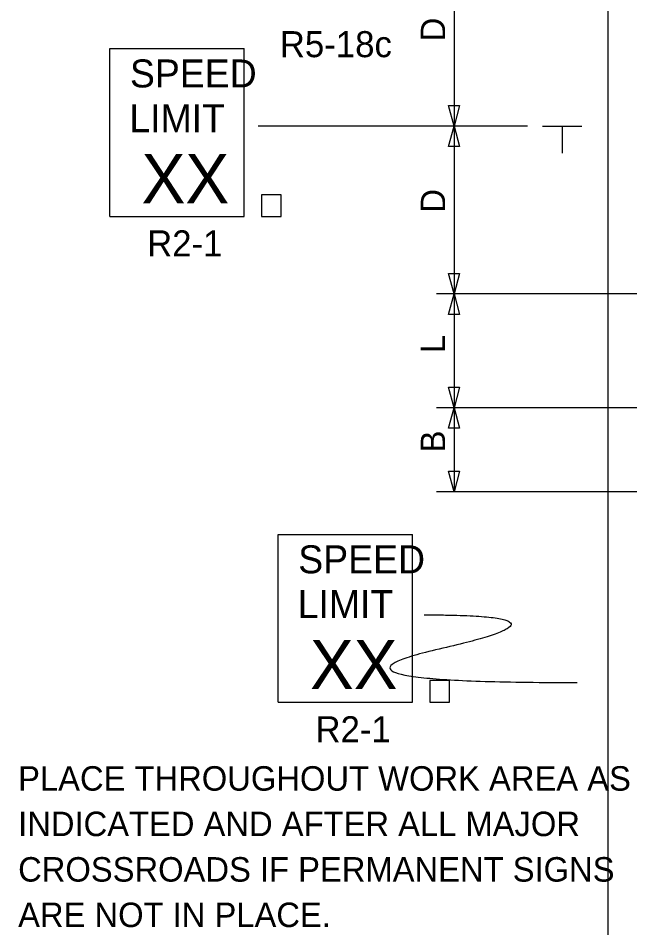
# Model space of a CAD drawing. Extents: x 16796 to 18475, y 7218 to 8209.
# Drawn here: x 16800.6 to 16975.6, y 7711.6 to 7971.7 of the extents above; entities that cross this region are included whole.
import ezdxf

# ---------------------------------------------------------------- set-up
doc = ezdxf.new("R2010")
doc.units = 0
for name, color, linetype in [('PAVT_EDGE_EX', 7, 'Continuous'), ('TRAFFIC_SIGNS_PR', 7, 'Continuous'), ('TYPICAL_TEXT_DIMEN_PR', 7, 'Continuous')]:
    doc.layers.add(name, color=color, linetype=linetype)

msp = doc.modelspace()

# ---------------------------------------------------------------- linework, layer by layer
at = {"layer": 'PAVT_EDGE_EX'}
msp.add_line((16969.33, 8204.89), (16969.33, 7353.77), dxfattribs=at)
at = {"layer": 'TRAFFIC_SIGNS_PR'}
for p, q in [((16826.84, 7963), (16865.24, 7963)), ((16826.84, 7915), (16826.84, 7963)), ((16865.24, 7915), (16865.24, 7963)), ((16826.84, 7915), (16865.24, 7915)), ((16875, 7824.09), (16913.4, 7824.09)), ((16875, 7776.09), (16875, 7824.09)), ((16913.4, 7776.09), (16913.4, 7824.09)), ((16875, 7776.09), (16913.4, 7776.09))]:
    msp.add_line(p, q, dxfattribs=at)
for points in [[(16870.26, 7915), (16875.85, 7915), (16875.85, 7921.17), (16870.26, 7921.17)], [(16918.41, 7776.09), (16924.01, 7776.09), (16924.01, 7782.26), (16918.41, 7782.26)]]:
    msp.add_lwpolyline(points, close=True, dxfattribs=at)
msp.add_open_spline([(16916.81, 7801.07), (16964.05, 7801.07), (16879.03, 7781.72), (16960.51, 7781.72)], degree=2, dxfattribs=at)
at = {"layer": 'TYPICAL_TEXT_DIMEN_PR'}
for p, q in [((16925.33, 7990.83), (16925.33, 7940.83)), ((16925.33, 7940.83), (16923.76, 7946.69)), ((16923.76, 7946.69), (16925.33, 7946.69)), ((16925.33, 7946.69), (16926.9, 7946.69)), ((16926.9, 7946.69), (16925.33, 7940.83)), ((16946.33, 7940.83), (16869.32, 7940.83)), ((16923.76, 7934.97), (16925.33, 7940.83)), ((16925.33, 7940.83), (16925.33, 7892.85)), ((16925.33, 7940.83), (16926.9, 7934.97)), ((16950.58, 7940.83), (16961.83, 7940.83)), ((16956.21, 7940.83), (16956.21, 7933.05)), ((16925.33, 7934.97), (16923.76, 7934.97)), ((16926.9, 7934.97), (16925.33, 7934.97)), ((16925.33, 7892.85), (16923.76, 7898.71)), ((16923.76, 7898.71), (16925.33, 7898.71)), ((16925.33, 7892.85), (16923.76, 7898.71)), ((16923.76, 7898.71), (16925.33, 7898.71)), ((16925.33, 7898.71), (16926.9, 7898.71)), ((16926.9, 7898.71), (16925.33, 7892.85)), ((16925.33, 7898.71), (16926.9, 7898.71)), ((16926.9, 7898.71), (16925.33, 7892.85)), ((17029.14, 7892.85), (16920.33, 7892.85)), ((16923.76, 7886.98), (16925.33, 7892.85)), ((16923.76, 7886.98), (16925.33, 7892.85)), ((16925.33, 7892.85), (16925.33, 7860.29)), ((16925.33, 7892.85), (16926.9, 7886.98)), ((16925.33, 7892.85), (16926.9, 7886.98)), ((16925.33, 7886.98), (16923.76, 7886.98)), ((16925.33, 7886.98), (16923.76, 7886.98)), ((16926.9, 7886.98), (16925.33, 7886.98)), ((16926.9, 7886.98), (16925.33, 7886.98)), ((16925.33, 7860.29), (16923.76, 7866.15)), ((16923.76, 7866.15), (16925.33, 7866.15)), ((16925.33, 7860.29), (16923.76, 7866.15)), ((16923.76, 7866.15), (16925.33, 7866.15)), ((16925.33, 7866.15), (16926.9, 7866.15)), ((16926.9, 7866.15), (16925.33, 7860.29)), ((16925.33, 7866.15), (16926.9, 7866.15)), ((16926.9, 7866.15), (16925.33, 7860.29)), ((17003.99, 7860.29), (16920.33, 7860.29)), ((16923.76, 7854.43), (16925.33, 7860.29)), ((16923.76, 7854.43), (16925.33, 7860.29)), ((16925.33, 7860.29), (16925.33, 7836.29)), ((16925.33, 7860.29), (16926.9, 7854.43)), ((16925.33, 7860.29), (16926.9, 7854.43)), ((16925.33, 7854.43), (16923.76, 7854.43)), ((16925.33, 7854.43), (16923.76, 7854.43)), ((16926.9, 7854.43), (16925.33, 7854.43)), ((16926.9, 7854.43), (16925.33, 7854.43)), ((16925.33, 7836.29), (16923.76, 7842.15)), ((16923.76, 7842.15), (16925.33, 7842.15)), ((16925.33, 7836.29), (16923.76, 7842.15)), ((16923.76, 7842.15), (16925.33, 7842.15)), ((16925.33, 7842.15), (16926.9, 7842.15)), ((16926.9, 7842.15), (16925.33, 7836.29)), ((16925.33, 7842.15), (16926.9, 7842.15)), ((16926.9, 7842.15), (16925.33, 7836.29)), ((17003.99, 7836.29), (16920.33, 7836.29))]:
    msp.add_line(p, q, dxfattribs=at)

# ---------------------------------------------------------------- texts
at = {"layer": 'TRAFFIC_SIGNS_PR'}
for s, height, p in [('R5-18c', 7.44, (16875.47, 7960.51)), ('SPEED', 8, (16832.61, 7951.86)), ('LIMIT', 8, (16832.45, 7939.06)), ('XX', 14.031, (16835.96, 7918.76)), ('R2-1', 7.44, (16837.52, 7903.56)), ('SPEED', 8, (16880.76, 7812.95)), ('LIMIT', 8, (16880.6, 7800.15)), ('XX', 14.031, (16884.11, 7779.85)), ('R2-1', 7.44, (16885.67, 7764.65)), ('PLACE THROUGHOUT WORK AREA AS', 7, (16800.63, 7750.81)), ('INDICATED AND AFTER ALL MAJOR', 7, (16800.63, 7737.81)), ('CROSSROADS IF PERMANENT SIGNS', 7, (16800.63, 7724.81)), ('ARE NOT IN PLACE.', 7, (16800.63, 7711.81))]:
    msp.add_text(s, height=height, dxfattribs=at).set_placement(p)
at = {"layer": 'TYPICAL_TEXT_DIMEN_PR'}
for s, p in [('D', (16922.78, 7965.05)), ('D', (16922.78, 7916.06)), ('L', (16922.78, 7875.93)), ('B', (16922.78, 7847.53))]:
    msp.add_text(s, height=7, rotation=90, dxfattribs=at).set_placement(p)

doc.saveas('drawing.dxf')
